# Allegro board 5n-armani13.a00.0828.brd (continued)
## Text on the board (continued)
VCC: list("[Spacing] VCC" "47.Shape to Route Keepin" "0 MIL [DEFAULT]" "0 MIL" "0.00 MIL" "DRC ERROR CLASS/VCC" "[Shape] Route Keepin/All ((-191.01 273.9) (8699.38 4792.96))" "[Vcc Shape] GND ((-191.01 273.9) (8699.38 4792.96))" list(-172.450000 3468.870000) nil)@@@list("iris_chen" "2017/08/23 17:49:25" nil "P16C000357-PC" "5n-armani13.a00")@@@list("anson_lee" "2017/08/24 14:21:24" nil "P172000029-PC" "5n-armani13.a00.0824") | list("[Spacing] VCC" "54.Shape to Route Keepin" "0 MIL [DEFAULT]" "0 MIL" "0.00 MIL" "DRC ERROR CLASS/VCC" "[Shape] Route Keepin/All ((-191.01 273.9) (8699.38 4792.96))" "[Vcc Shape] AGND ((-137.46 1141.0) (434.0 2428.0))" list(-129.620000 2286.830000) nil)@@@list("iris_chen" "2017/08/22 17:13:19" nil "P16C000357-PC" "5n-armani13.a00")@@@list("anson_lee" "2017/08/24 14:21:29" nil "P172000029-PC" "5n-armani13.a00.0824") | list("[Spacing] VCC" "143.Thru Pin to Shape" "5 MIL [DEFAULT]" "0 MIL" "5.00 MIL" "DRC ERROR CLASS/VCC" "[ThruPin] GND (<uTiL>cId30<uTiL>.51) (380.5 1405.0)" "[Vcc Shape] +5VSB ((381.0 745.0) (7865.0 3971.0))" list(381.000000 1416.990000) nil)@@@list("iris_chen" "2017/08/22 17:17:54" nil "P16C000357-PC" "5n-armani13.a00")@@@list("anson_lee" "2017/08/24 14:22:26" nil "P172000029-PC" "5n-armani13.a00.0824") | list("[Spacing] VCC" "142.Thru Pin to Shape" "5 MIL [DEFAULT]" "0 MIL" "5.00 MIL" "DRC ERROR CLASS/VCC" "[ThruPin] GND (<uTiL>cId30<uTiL>.52) (380.5 1325.5)" "[Vcc Shape] +5VSB ((381.0 745.0) (7865.0 3971.0))" list(381.000000 1337.490000) nil)@@@list("iris_chen" "2017/08/22 17:17:54" nil "P16C000357-PC" "5n-armani13.a00")@@@list("anson_lee" "2017/08/24 14:22:25" nil "P172000029-PC" "5n-armani13.a00.0824") | list("[Spacing] VCC" "145.Thru Pin to Shape" "5 MIL [DEFAULT]" "0 MIL" "5.00 MIL" "DRC ERROR CLASS/VCC" "[ThruPin] GND (<uTiL>cId30<uTiL>.50) (380.5 1484.5)" "[Vcc Shape] +5VSB ((381.0 745.0) (7865.0 3971.0))" list(392.490000 1484.000000) nil)@@@list("iris_chen" "2017/08/22 17:17:55" nil "P16C000357-PC" "5n-armani13.a00")@@@list("anson_lee" "2017/08/24 14:22:36" nil "P172000029-PC" "5n-armani13.a00.0824") | list("[Spacing] VCC" "96.Shape to Thru Via" "5 MIL [DEFAULT]" "0 MIL" "5.00 MIL" "DRC ERROR CLASS/VCC" "[ThruVia] DP2_MUX (VIA20D10A30) (401.0 3686.0)" "[Vcc Shape] +USB_TYPEC ((30.0 3558.96) (393.07 3902.29))" list(393.070000 3692.090000) nil)@@@list("iris_chen" "2017/08/22 17:13:04" nil "P16C000357-PC" "5n-armani13.a00")@@@list("anson_lee" "2017/08/24 14:21:54" nil "P172000029-PC" "5n-armani13.a00.0824") | list("[Spacing] VCC" "44.Shape to Thru Via" "5 MIL [DEFAULT]" "0 MIL" "5.00 MIL" "DRC ERROR CLASS/VCC" "[ThruVia] DP2_MUX (VIA20D10A30) (401.0 3686.0)" "[Vcc Shape] GND ((-191.01 273.9) (8699.38 4792.96))" list(403.070000 3695.780000) nil)@@@list("iris_chen" "2017/08/22 17:13:25" nil "P16C000357-PC" "5n-armani13.a00")@@@list("anson_lee" "2017/08/24 14:21:22" nil "P172000029-PC" "5n-armani13.a00.0824") | list("[Spacing-SameNet] VCC" "189.Shape to Thru Via Same Net" "5 MIL [DEFAULT]" "0 MIL" "5.00 MIL" "DRC ERROR CLASS/VCC" "[ThruVia] GND (VIA20D10A30) (455.0 3250.0)" "[Vcc Shape] GND ((-191.01 273.9) (8699.38 4792.96))" list(451.000000 3259.170000) nil)@@@list("iris_chen" "2017/08/22 17:18:45" nil "P16C000357-PC" "5n-armani13.a00")@@@list("anson_lee" "2017/08/24 14:23:58" nil "P172000029-PC" "5n-armani13.a00.0824") | list("[Spacing-SameNet] VCC" "190.Shape to Thru Via Same Net" "5 MIL [DEFAULT]" "0 MIL" "5.00 MIL" "DRC ERROR CLASS/VCC" "[ThruVia] GND (VIA20D10A30) (456.54 3173.14)" "[Vcc Shape] GND ((-191.01 273.9) (8699.38 4792.96))" list(451.000000 3181.470000) nil)@@@list("iris_chen" "2017/08/22 17:18:45" nil "P16C000357-PC" "5n-armani13.a00")@@@list("anson_lee" "2017/08/24 14:23:59" nil "P172000029-PC" "5n-armani13.a00.0824") | list("[Spacing] VCC" "147.Shape to Thru Via" "5 MIL [DEFAULT]" "0 MIL" "5.00 MIL" "DRC ERROR CLASS/VCC" "[ThruVia] GND (VIA20D10A30) (455.0 3250.0)" "[Vcc Shape] +5VSB ((381.0 745.0) (7865.0 3971.0))" list(461.000000 3258.000000) nil)@@@list("iris_chen" "2017/08/22 17:17:56" nil "P16C000357-PC" "5n-armani13.a00")@@@list("anson_lee" "2017/08/24 14:22:38" nil "P172000029-PC" "5n-armani13.a00.0824") | list("[Spacing] VCC" "148.Shape to Thru Via" "5 MIL [DEFAULT]" "0 MIL" "5.00 MIL" "DRC ERROR CLASS/VCC" "[ThruVia] GND (VIA20D10A30) (456.54 3173.14)" "[Vcc Shape] +5VSB ((381.0 745.0) (7865.0 3971.0))" list(461.000000 3182.090000) nil)@@@list("iris_chen" "2017/08/22 17:17:57" nil "P16C000357-PC" "5n-armani13.a00")@@@list("anson_lee" "2017/08/24 14:22:38" nil "P172000029-PC" "5n-armani13.a00.0824") | list("[Spacing-SameNet] VCC" "192.Thru Pin to Shape Same Net" "5 MIL [DEFAULT]" "0 MIL" "5.00 MIL" "DRC ERROR CLASS/VCC" "[ThruPin] GND (<uTiL>cId2509<uTiL>.23) (504.69 3399.31)" "[Vcc Shape] GND ((-191.01 273.9) (8699.38 4792.96))" list(492.750000 3400.470000) nil)@@@list("iris_chen" "2017/08/22 17:18:46" nil "P16C000357-PC" "5n-armani13.a00")@@@list("anson_lee" "2017/08/24 14:24:00" nil "P172000029-PC" "5n-armani13.a00.0824") | list("[Spacing-SameNet] VCC" "191.Thru Pin to Shape Same Net" "5 MIL [DEFAULT]" "0 MIL" "5.00 MIL" "DRC ERROR CLASS/VCC" "[ThruPin] GND (<uTiL>cId2509<uTiL>.26) (504.69 3438.69)" "[Vcc Shape] GND ((-191.01 273.9) (8699.38 4792.96))" list(496.000000 3446.970000) nil)@@@list("iris_chen" "2017/08/22 17:18:45" nil "P16C000357-PC" "5n-armani13.a00")@@@list("anson_lee" "2017/08/24 14:23:59" nil "P172000029-PC" "5n-armani13.a00.0824") | list("[Spacing] VCC" "149.Thru Pin to Shape" "5 MIL [DEFAULT]" "0 MIL" "5.00 MIL" "DRC ERROR CLASS/VCC" "[ThruPin] GND (<uTiL>cId2509<uTiL>.26) (504.69 3438.69)" "[Vcc Shape] +5VSB ((381.0 745.0) (7865.0 3971.0))" list(506.000000 3450.620000) nil)@@@list("iris_chen" "2017/08/22 17:17:57" nil "P16C000357-PC" "5n-armani13.a00")@@@list("anson_lee" "2017/08/24 14:22:39" nil "P172000029-PC" "5n-armani13.a00.0824") | list("[Spacing] VCC" "150.Thru Pin to Shape" "5 MIL [DEFAULT]" "0 MIL" "5.00 MIL" "DRC ERROR CLASS/VCC" "[ThruPin] GND (<uTiL>cId2509<uTiL>.23) (504.69 3399.31)" "[Vcc Shape] +5VSB ((381.0 745.0) (7865.0 3971.0))" list(506.000000 3411.240000) nil)@@@list("iris_chen" "2017/08/22 17:17:58" nil "P16C000357-PC" "5n-armani13.a00")@@@list("anson_lee" "2017/08/24 14:22:40" nil "P172000029-PC" "5n-armani13.a00.0824") | list("[Spacing] VCC" "134.Shape to Thru Via" "5 MIL [DEFAULT]" "0 MIL" "5.00 MIL" "DRC ERROR CLASS/VCC" "[ThruVia] CHG_ACIN (VIA20D10A30) (847.0 1064.0)" "[Vcc Shape] +5VSB ((381.0 745.0) (7865.0 3971.0))" list(855.000000 1070.000000) nil)@@@list("iris_chen" "2017/08/22 17:17:50" nil "P16C000357-PC" "5n-armani13.a00")@@@list("anson_lee" "2017/08/24 14:22:21" nil "P172000029-PC" "5n-armani13.a00.0824") | list("[Spacing] VCC" "43.Shape to Thru Via" "5 MIL [DEFAULT]" "0 MIL" "5.00 MIL" "DRC ERROR CLASS/VCC" "[ThruVia] CHG_ACIN (VIA20D10A30) (847.0 1064.0)" "[Vcc Shape] GND ((-191.01 273.9) (8699.38 4792.96))" list(856.170000 1060.000000) nil)@@@list("iris_chen" "2017/08/22 17:13:24" nil "P16C000357-PC" "5n-armani13.a00")@@@list("anson_lee" "2017/08/24 14:21:22" nil "P172000029-PC" "5n-armani13.a00.0824") | list("[Spacing] VCC" "48.Shape to Thru Via" "5 MIL [DEFAULT]" "0 MIL" "5.00 MIL" "DRC ERROR CLASS/VCC" "[ThruVia] HDMI_HPD_SNK (VIA20D10A30) (954.0 2921.0)" "[Vcc Shape] +1P8VSB ((880.0 2930.0) (3605.0 4684.0))" list(958.360000 2930.000000) nil)@@@list("iris_chen" "2017/08/22 17:13:27" nil "P16C000357-PC" "5n-armani13.a00")@@@list("anson_lee" "2017/08/24 14:21:25" nil "P172000029-PC" "5n-armani13.a00.0824") | list("[Spacing] VCC" "124.Shape to Thru Via" "5 MIL [DEFAULT]" "0 MIL" "5.00 MIL" "DRC ERROR CLASS/VCC" "[ThruVia] HDMI_HPD_SNK (VIA20D10A30) (954.0 2921.0)" "[Vcc Shape] +3P3VSB ((926.0 394.17) (8430.0 4743.0))" list(963.950000 2920.000000) nil)@@@list("iris_chen" "2017/08/22 17:18:16" nil "P16C000357-PC" "5n-armani13.a00")@@@list("anson_lee" "2017/08/24 14:22:16" nil "P172000029-PC" "5n-armani13.a00.0824") | list("[Spacing] VCC" "77.Shape to Thru Via" "5 MIL [DEFAULT]" "0 MIL" "5.00 MIL" "DRC ERROR CLASS/VCC" "[ThruVia] +VCCPLL_OC (VIA20D10A30) (1048.0 2923.0)" "[Vcc Shape] +1P8VSB ((880.0 2930.0) (3605.0 4684.0))" list(1055.140000 2930.000000) nil)@@@list("iris_chen" "2017/08/22 17:13:28" nil "P16C000357-PC" "5n-armani13.a00")@@@nil | list("[Spacing] VCC" "141.Shape to Thru Via" "5 MIL [DEFAULT]" "0 MIL" "5.00 MIL" "DRC ERROR CLASS/VCC" "[ThruVia] +VCCPLL_OC (VIA20D10A30) (1048.0 2923.0)" "[Vcc Shape] +3P3VSB ((926.0 394.17) (8430.0 4743.0))" list(1057.540000 2920.000000) nil)@@@list("iris_chen" "2017/08/22 17:18:16" nil "P16C000357-PC" "5n-armani13.a00")@@@nil | list("[Spacing] VCC" "50.Shape to Thru Via" "5 MIL [DEFAULT]" "0 MIL" "5.00 MIL" "DRC ERROR CLASS/VCC" "[ThruVia] +VDC_IN (VIA20D10A30) (1266.0 3886.0)" "[Vcc Shape] +1P8VSB ((880.0 2930.0) (3605.0 4684.0))" list(1265.000000 3895.950000) nil)@@@list("iris_chen" "2017/08/22 17:17:46" nil "P16C000357-PC" "5n-armani13.a00")@@@list("anson_lee" "2017/08/24 14:21:26" nil "P172000029-PC" "5n-armani13.a00.0824") | list("[Spacing] VCC" "49.Shape to Thru Via" "5 MIL [DEFAULT]" "0 MIL" "5.00 MIL" "DRC ERROR CLASS/VCC" "[ThruVia] GND (VIA20D10A30) (1269.0 3139.0)" "[Vcc Shape] +1P8VSB ((880.0 2930.0) (3605.0 4684.0))" list(1265.000000 3148.170000) nil)@@@list("iris_chen" "2017/08/22 17:17:45" nil "P16C000357-PC" "5n-armani13.a00")@@@list("anson_lee" "2017/08/24 14:21:26" nil "P172000029-PC" "5n-armani13.a00.0824") | list("[Spacing] VCC" "128.Shape to Thru Via" "5 MIL [DEFAULT]" "0 MIL" "5.00 MIL" "DRC ERROR CLASS/VCC" "[ThruVia] +VDC_IN (VIA20D10A30) (1266.0 3886.0)" "[Vcc Shape] +3P3VSB ((926.0 394.17) (8430.0 4743.0))" list(1275.000000 3890.360000) nil)@@@list("iris_chen" "2017/08/22 17:18:18" nil "P16C000357-PC" "5n-armani13.a00")@@@list("anson_lee" "2017/08/24 14:22:18" nil "P172000029-PC" "5n-armani13.a00.0824") | list("[Spacing] VCC" "125.Shape to Thru Via" "5 MIL [DEFAULT]" "0 MIL" "5.00 MIL" "DRC ERROR CLASS/VCC" "[ThruVia] GND (VIA20D10A30) (1269.0 3139.0)" "[Vcc Shape] +3P3VSB ((926.0 394.17) (8430.0 4743.0))" list(1275.000000 3147.000000) nil)@@@list("iris_chen" "2017/08/22 17:18:17" nil "P16C000357-PC" "5n-armani13.a00")@@@list("anson_lee" "2017/08/24 14:22:16" nil "P172000029-PC" "5n-armani13.a00.0824") | list("[Spacing] VCC" "51.Shape to Thru Via" "5 MIL [DEFAULT]" "0 MIL" "5.00 MIL" "DRC ERROR CLASS/VCC" "[ThruVia] USB_ADT (VIA20D10A30) (1335.0 4439.0)" "[Vcc Shape] +1P8VSB ((880.0 2930.0) (3605.0 4684.0))" list(1343.000000 4445.000000) nil)@@@list("iris_chen" "2017/08/22 17:17:47" nil "P16C000357-PC" "5n-armani13.a00")@@@list("anson_lee" "2017/08/24 14:21:27" nil "P172000029-PC" "5n-armani13.a00.0824") | list("[Spacing] VCC" "129.Shape to Thru Via" "5 MIL [DEFAULT]" "0 MIL" "5.00 MIL" "DRC ERROR CLASS/VCC" "[ThruVia] USB_ADT (VIA20D10A30) (1335.0 4439.0)" "[Vcc Shape] +3P3VSB ((926.0 394.17) (8430.0 4743.0))" list(1344.170000 4435.000000) nil)@@@list("iris_chen" "2017/08/22 17:18:19" nil "P16C000357-PC" "5n-armani13.a00")@@@list("anson_lee" "2017/08/24 14:22:18" nil "P172000029-PC" "5n-armani13.a00.0824") | list("[Spacing] VCC" "144.Shape to Thru Via" "5 MIL [DEFAULT]" "0 MIL" "5.00 MIL" "DRC ERROR CLASS/VCC" "[ThruVia] +3VALW_EC (VIA20D10A30) (1565.0 1414.0)" "[Vcc Shape] +5VSB ((381.0 745.0) (7865.0 3971.0))" list(1568.350000 1404.580000) nil)@@@list("iris_chen" "2017/08/22 17:17:55" nil "P16C000357-PC" "5n-armani13.a00")@@@list("anson_lee" "2017/08/24 14:22:26" nil "P172000029-PC" "5n-armani13.a00.0824") | list("[Spacing] VCC" "121.Shape to Thru Via" "5 MIL [DEFAULT]" "0 MIL" "5.00 MIL" "DRC ERROR CLASS/VCC" "[ThruVia] +3VALW_EC (VIA20D10A30) (1565.0 1414.0)" "[Vcc Shape] +3P3VSB ((926.0 394.17) (8430.0 4743.0))" list(1574.840000 1412.240000) nil)@@@list("iris_chen" "2017/08/22 17:18:13" nil "P16C000357-PC" "5n-armani13.a00")@@@list("anson_lee" "2017/08/24 14:22:14" nil "P172000029-PC" "5n-armani13.a00.0824") | list("[Spacing] VCC" "109.Shape to Thru Via" "5 MIL [DEFAULT]" "0 MIL" "5.00 MIL" "DRC ERROR CLASS/VCC" "[ThruVia] GND (VIA20D10A30) (1789.09 521.9)" "[Vcc Shape] +3P3VSB ((926.0 394.17) (8430.0 4743.0))" list(1796.330000 515.000000) nil)@@@list("iris_chen" "2017/08/22 17:18:08" nil "P16C000357-PC" "5n-armani13.a00")@@@list("anson_lee" "2017/08/24 14:22:03" nil "P172000029-PC" "5n-armani13.a00.0824") | list("[Spacing] VCC" "61.Shape to Thru Via" "5 MIL [DEFAULT]" "0 MIL" "5.00 MIL" "DRC ERROR CLASS/VCC" "[ThruVia] GND (VIA20D10A30) (1789.09 521.9)" "[Vcc Shape] +5V ((625.0 525.0) (8000.0 2265.0))" list(1798.600000 525.000000) nil)@@@list("iris_chen" "2017/08/22 17:13:05" nil "P16C000357-PC" "5n-armani13.a00")@@@list("anson_lee" "2017/08/24 14:21:33" nil "P172000029-PC" "5n-armani13.a00.0824") | list("[Spacing] VCC" "108.Shape to Thru Via" "5 MIL [DEFAULT]" "0 MIL" "5.00 MIL" "DRC ERROR CLASS/VCC" "[ThruVia] +3P3V_PAD (VIA20D10A30) (1814.0 524.76)" "[Vcc Shape] +3P3VSB ((926.0 394.17) (8430.0 4743.0))" list(1816.180000 515.000000) nil)@@@list("iris_chen" "2017/08/22 17:18:07" nil "P16C000357-PC" "5n-armani13.a00")@@@list("anson_lee" "2017/08/24 14:22:02" nil "P172000029-PC" "5n-armani13.a00.0824") | list("[Spacing] VCC" "60.Shape to Thru Via" "5 MIL [DEFAULT]" "0 MIL" "5.00 MIL" "DRC ERROR CLASS/VCC" "[ThruVia] +3P3V_PAD (VIA20D10A30) (1814.0 524.76)" "[Vcc Shape] +5V ((625.0 525.0) (8000.0 2265.0))" list(1824.000000 525.000000) nil)@@@list("iris_chen" "2017/08/22 17:13:04" nil "P16C000357-PC" "5n-armani13.a00")@@@list("anson_lee" "2017/08/24 14:21:33" nil "P172000029-PC" "5n-armani13.a00.0824") | list("[Spacing] VCC" "110.Shape to Thru Via" "5 MIL [DEFAULT]" "0 MIL" "5.00 MIL" "DRC ERROR CLASS/VCC" "[ThruVia] +3P3V_PAD (VIA20D10A30) (1860.0 524.0)" "[Vcc Shape] +3P3VSB ((926.0 394.17) (8430.0 4743.0))" list(1864.360000 515.000000) nil)@@@list("iris_chen" "2017/08/22 17:18:08" nil "P16C000357-PC" "5n-armani13.a00")@@@list("anson_lee" "2017/08/24 14:22:04" nil "P172000029-PC" "5n-armani13.a00.0824") | list("[Spacing] VCC" "62.Shape to Thru Via" "5 MIL [DEFAULT]" "0 MIL" "5.00 MIL" "DRC ERROR CLASS/VCC" "[ThruVia] +3P3V_PAD (VIA20D10A30) (1860.0 524.0)" "[Vcc Shape] +5V ((625.0 525.0) (8000.0 2265.0))" list(1869.950000 525.000000) nil)@@@list("iris_chen" "2017/08/22 17:13:06" nil "P16C000357-PC" "5n-armani13.a00")@@@list("anson_lee" "2017/08/24 14:21:34" nil "P172000029-PC" "5n-armani13.a00.0824") | list("[Spacing] VCC" "111.Shape to Thru Via" "5 MIL [DEFAULT]" "0 MIL" "5.00 MIL" "DRC ERROR CLASS/VCC" "[ThruVia] GND (VIA20D10A30) (1895.0 522.0)" "[Vcc Shape] +3P3VSB ((926.0 394.17) (8430.0 4743.0))" list(1902.140000 515.000000) nil)@@@list("iris_chen" "2017/08/22 17:18:08" nil "P16C000357-PC" "5n-armani13.a00")@@@list("anson_lee" "2017/08/24 14:22:04" nil "P172000029-PC" "5n-armani13.a00.0824") | list("[Spacing] VCC" "63.Shape to Thru Via" "5 MIL [DEFAULT]" "0 MIL" "5.00 MIL" "DRC ERROR CLASS/VCC" "[ThruVia] GND (VIA20D10A30) (1895.0 522.0)" "[Vcc Shape] +5V ((625.0 525.0) (8000.0 2265.0))" list(1904.540000 525.000000) nil)@@@list("iris_chen" "2017/08/22 17:13:06" nil "P16C000357-PC" "5n-armani13.a00")@@@list("anson_lee" "2017/08/24 14:21:34" nil "P172000029-PC" "5n-armani13.a00.0824") | list("[Spacing] VCC" "112.Shape to Thru Via" "5 MIL [DEFAULT]" "0 MIL" "5.00 MIL" "DRC ERROR CLASS/VCC" "[ThruVia] GND (VIA20D10A30) (2015.0 524.0)" "[Vcc Shape] +3P3VSB ((926.0 394.17) (8430.0 4743.0))" list(2019.360000 515.000000) nil)@@@list("iris_chen" "2017/08/22 17:18:09" nil "P16C000357-PC" "5n-armani13.a00")@@@list("anson_lee" "2017/08/24 14:22:06" nil "P172000029-PC" "5n-armani13.a00.0824") | list("[Spacing] VCC" "64.Shape to Thru Via" "5 MIL [DEFAULT]" "0 MIL" "5.00 MIL" "DRC ERROR CLASS/VCC" "[ThruVia] GND (VIA20D10A30) (2015.0 524.0)" "[Vcc Shape] +5V ((625.0 525.0) (8000.0 2265.0))" list(2024.950000 525.000000) nil)@@@list("iris_chen" "2017/08/22 17:13:07" nil "P16C000357-PC" "5n-armani13.a00")@@@list("anson_lee" "2017/08/24 14:21:35" nil "P172000029-PC" "5n-armani13.a00.0824") | list("[Spacing] VCC" "45.Shape to Thru Via" "5 MIL [DEFAULT]" "0 MIL" "5.00 MIL" "DRC ERROR CLASS/VCC" "[ThruVia] AD_OFF_R (VIA20D10A30) (2034.0 4606.0)" "[Vcc Shape] GND ((-191.01 273.9) (8699.38 4792.96))" list(2042.000000 4612.000000) nil)@@@list("iris_chen" "2017/08/22 17:13:25" nil "P16C000357-PC" "5n-armani13.a00")@@@list("anson_lee" "2017/08/24 14:21:23" nil "P172000029-PC" "5n-armani13.a00.0824") | list("[Spacing] VCC" "52.Shape to Thru Via" "5 MIL [DEFAULT]" "0 MIL" "5.00 MIL" "DRC ERROR CLASS/VCC" "[ThruVia] AD_OFF_R (VIA20D10A30) (2034.0 4606.0)" "[Vcc Shape] +1P8VSB ((880.0 2930.0) (3605.0 4684.0))" list(2043.170000 4602.000000) nil)@@@list("iris_chen" "2017/08/22 17:17:48" nil "P16C000357-PC" "5n-armani13.a00")@@@list("anson_lee" "2017/08/24 14:21:27" nil "P172000029-PC" "5n-armani13.a00.0824") | list("[Spacing] VCC" "114.Shape to Thru Via" "5 MIL [DEFAULT]" "0 MIL" "5.00 MIL" "DRC ERROR CLASS/VCC" "[ThruVia] RESET_OUT# (VIA20D10A30) (2069.0 1059.3)" "[Vcc Shape] +3P3VSB ((926.0 394.17) (8430.0 4743.0))" list(2077.220000 1065.000000) nil)@@@list("iris_chen" "2017/08/22 17:18:10" nil "P16C000357-PC" "5n-armani13.a00")@@@list("anson_lee" "2017/08/24 14:22:10" nil "P172000029-PC" "5n-armani13.a00.0824") | list("[Spacing] VCC" "135.Shape to Thru Via" "5 MIL [DEFAULT]" "0 MIL" "5.00 MIL" "DRC ERROR CLASS/VCC" "[ThruVia] RESET_OUT# (VIA20D10A30) (2069.0 1059.3)" "[Vcc Shape] +5VSB ((381.0 745.0) (7865.0 3971.0))" list(2078.030000 1055.000000) nil)@@@list("iris_chen" "2017/08/22 17:17:50" nil "P16C000357-PC" "5n-armani13.a00")@@@list("anson_lee" "2017/08/24 14:22:21" nil "P172000029-PC" "5n-armani13.a00.0824") | list("[Spacing] VCC" "46.Shape to Thru Via" "5 MIL [DEFAULT]" "0 MIL" "5.00 MIL" "DRC ERROR CLASS/VCC" "[ThruVia] N146992205 (VIA20D10A30) (2568.0 4606.0)" "[Vcc Shape] GND ((-191.01 273.9) (8699.38 4792.96))" list(2576.000000 4612.000000) nil)@@@list("iris_chen" "2017/08/22 17:13:26" nil "P16C000357-PC" "5n-armani13.a00")@@@list("anson_lee" "2017/08/24 14:21:24" nil "P172000029-PC" "5n-armani13.a00.0824") | list("[Spacing] VCC" "53.Shape to Thru Via" "5 MIL [DEFAULT]" "0 MIL" "5.00 MIL" "DRC ERROR CLASS/VCC" "[ThruVia] N146992205 (VIA20D10A30) (2568.0 4606.0)" "[Vcc Shape] +1P8VSB ((880.0 2930.0) (3605.0 4684.0))" list(2577.170000 4602.000000) nil)@@@list("iris_chen" "2017/08/22 17:17:48" nil "P16C000357-PC" "5n-armani13.a00")@@@list("anson_lee" "2017/08/24 14:21:28" nil "P172000029-PC" "5n-armani13.a00.0824") | list("[Spacing] VCC" "115.Shape to Thru Via" "5 MIL [DEFAULT]" "0 MIL" "5.00 MIL" "DRC ERROR CLASS/VCC" "[ThruVia] +1P8V (VIA30D18A40) (3275.0 1142.0)" "[Vcc Shape] +3P3VSB ((926.0 394.17) (8430.0 4743.0))" list(3288.270000 1149.000000) nil)@@@list("iris_chen" "2017/08/22 17:18:10" nil "P16C000357-PC" "5n-armani13.a00")@@@list("anson_lee" "2017/08/24 14:22:11" nil "P172000029-PC" "5n-armani13.a00.0824") | list("[Spacing] VCC" "136.Shape to Thru Via" "5 MIL [DEFAULT]" "0 MIL" "5.00 MIL" "DRC ERROR CLASS/VCC" "[ThruVia] +1P8V (VIA30D18A40) (3275.0 1142.0)" "[Vcc Shape] +5VSB ((381.0 745.0) (7865.0 3971.0))" list(3289.700000 1139.000000) nil)@@@list("iris_chen" "2017/08/22 17:17:51" nil "P16C000357-PC" "5n-armani13.a00")@@@list("anson_lee" "2017/08/24 14:22:22" nil "P172000029-PC" "5n-armani13.a00.0824") | list("[Spacing] VCC" "75.Shape to Route Keepin" "0 MIL [DEFAULT]" "0 MIL" "0.00 MIL" "DRC ERROR CLASS/VCC" "[Shape] Route Keepin/All ((-191.01 273.9) (8699.38 4792.96))" "[Vcc Shape] GND ((-191.01 273.9) (8699.38 4792.96))" list(3404.430000 4702.410000) nil)@@@list("iris_chen" "2017/08/22 17:13:26" nil "P16C000357-PC" "5n-armani13.a00")@@@nil | list("[Spacing-SameNet] VCC" "194.Shape to Thru Via Same Net" "5 MIL [DEFAULT]" "0 MIL" "5.00 MIL" "DRC ERROR CLASS/VCC" "[ThruVia] GND (VIA18D10A28) (3880.45 2091.55)" "[Vcc Shape] GND ((2160.0 1185.0) (4422.0 3926.0))" list(3872.390000 2095.540000) nil)@@@list("iris_chen" "2017/08/22 17:18:44" nil "P16C000357-PC" "5n-armani13.a00")@@@list("anson_lee" "2017/08/24 14:24:01" nil "P172000029-PC" "5n-armani13.a00.0824") | list("[Spacing] VCC" "57.Shape to Thru Via" "5 MIL [DEFAULT]" "0 MIL" "5.00 MIL" "DRC ERROR CLASS/VCC" "[ThruVia] +1P2V_DUAL (VIA18D10A28) (3883.0 2036.0)" "[Vcc Shape] GND ((2160.0 1185.0) (4422.0 3926.0))" list(3875.000000 2040.120000) nil)@@@list("iris_chen" "2017/08/22 17:13:21" nil "P16C000357-PC" "5n-armani13.a00")@@@list("anson_lee" "2017/08/24 14:21:31" nil "P172000029-PC" "5n-armani13.a00.0824") | list("[Spacing] VCC" "88.Shape to Thru Via" "5 MIL [DEFAULT]" "0 MIL" "5.00 MIL" "DRC ERROR CLASS/VCC" "[ThruVia] GND (VIA18D10A28) (3880.45 2091.55)" "[Vcc Shape] +VCCIO ((3836.0 1141.93) (5170.0 2510.0))" list(3881.600000 2100.480000) nil)@@@list("iris_chen" "2017/08/22 17:18:04" nil "P16C000357-PC" "5n-armani13.a00")@@@list("anson_lee" "2017/08/24 14:21:48" nil "P172000029-PC" "5n-armani13.a00.0824") | list("[Spacing] VCC" "87.Shape to Thru Via" "5 MIL [DEFAULT]" "0 MIL" "5.00 MIL" "DRC ERROR CLASS/VCC" "[ThruVia] +1P2V_DUAL (VIA18D10A28) (3883.0 2036.0)" "[Vcc Shape] +VCCIO ((3836.0 1141.93) (5170.0 2510.0))" list(3885.000000 2044.770000) nil)@@@list("iris_chen" "2017/08/22 17:18:03" nil "P16C000357-PC" "5n-armani13.a00")@@@list("anson_lee" "2017/08/24 14:21:47" nil "P172000029-PC" "5n-armani13.a00.0824") | list("[Spacing] VCC" "59.Shape to Thru Via" "5 MIL [DEFAULT]" "0 MIL" "5.00 MIL" "DRC ERROR CLASS/VCC" "[ThruVia] SIO_SLP_S4# (VIA20D10A30) (3897.46 3779.46)" "[Vcc Shape] GND ((2160.0 1185.0) (4422.0 3926.0))" list(3900.110000 3769.820000) nil)@@@list("iris_chen" "2017/08/22 17:13:23" nil "P16C000357-PC" "5n-armani13.a00")@@@list("anson_lee" "2017/08/24 14:21:32" nil "P172000029-PC" "5n-armani13.a00.0824") | list("[Spacing] VCC" "127.Shape to Thru Via" "5 MIL [DEFAULT]" "0 MIL" "5.00 MIL" "DRC ERROR CLASS/VCC" "[ThruVia] SIO_SLP_S4# (VIA20D10A30) (3897.46 3779.46)" "[Vcc Shape] +3P3VSB ((926.0 394.17) (8430.0 4743.0))" list(3907.140000 3776.940000) nil)@@@list("iris_chen" "2017/08/22 17:18:18" nil "P16C000357-PC" "5n-armani13.a00")@@@list("anson_lee" "2017/08/24 14:22:17" nil "P172000029-PC" "5n-armani13.a00.0824") | list("[Spacing-SameNet] VCC" "195.Shape to Thru Via Same Net" "5 MIL [DEFAULT]" "0.88 MIL" "4.12 MIL" "DRC ERROR CLASS/VCC" "[ThruVia] GND (VIA18D10A28) (4019.88 2419.5)" "[Vcc Shape] GND ((2160.0 1185.0) (4422.0 3926.0))" list(4010.880000 2419.500000) nil)@@@list("iris_chen" "2017/08/22 17:18:44" nil "P16C000357-PC" "5n-armani13.a00")@@@list("anson_lee" "2017/08/24 14:24:02" nil "P172000029-PC" "5n-armani13.a00.0824") | list("[Spacing] VCC" "58.Shape to Thru Via" "5 MIL [DEFAULT]" "0 MIL" "5.00 MIL" "DRC ERROR CLASS/VCC" "[ThruVia] +1P2V_DUAL (VIA18D10A28) (4019.88 2456.0)" "[Vcc Shape] GND ((2160.0 1185.0) (4422.0 3926.0))" list(4011.150000 2458.200000) nil)@@@list("iris_chen" "2017/08/22 17:13:22" nil "P16C000357-PC" "5n-armani13.a00")@@@list("anson_lee" "2017/08/24 14:21:31" nil "P172000029-PC" "5n-armani13.a00.0824") | list("[Spacing] VCC" "89.Shape to Thru Via" "5 MIL [DEFAULT]" "0 MIL" "5.00 MIL" "DRC ERROR CLASS/VCC" "[ThruVia] +1P2V_DUAL (VIA18D10A28) (4019.88 2456.0)" "[Vcc Shape] +VCCIO ((3836.0 1141.93) (5170.0 2510.0))" list(4020.000000 2447.000000) nil)@@@list("iris_chen" "2017/08/22 17:18:04" nil "P16C000357-PC" "5n-armani13.a00")@@@list("anson_lee" "2017/08/24 14:21:49" nil "P172000029-PC" "5n-armani13.a00.0824") | list("[Spacing] VCC" "90.Shape to Thru Via" "5 MIL [DEFAULT]" "0 MIL" "5.00 MIL" "DRC ERROR CLASS/VCC" "[ThruVia] GND (VIA18D10A28) (4019.88 2419.5)" "[Vcc Shape] +VCCIO ((3836.0 1141.93) (5170.0 2510.0))" list(4020.000000 2428.500000) nil)@@@list("iris_chen" "2017/08/22 17:18:05" nil "P16C000357-PC" "5n-armani13.a00")@@@list("anson_lee" "2017/08/24 14:21:50" nil "P172000029-PC" "5n-armani13.a00.0824") | list("[Spacing] VCC" "120.Shape to Thru Via" "5 MIL [DEFAULT]" "0 MIL" "5.00 MIL" "DRC ERROR CLASS/VCC" "[ThruVia] +VCC_RTC_PCH (VIA20D10A30) (4067.0 1209.61)" "[Vcc Shape] +3P3VSB ((926.0 394.17) (8430.0 4743.0))" list(4069.770000 1200.000000) nil)@@@list("iris_chen" "2017/08/22 17:18:13" nil "P16C000357-PC" "5n-armani13.a00")@@@list("anson_lee" "2017/08/24 14:22:14" nil "P172000029-PC" "5n-armani13.a00.0824") | list("[Spacing] VCC" "84.Shape to Thru Via" "5 MIL [DEFAULT]" "0 MIL" "5.00 MIL" "DRC ERROR CLASS/VCC" "[ThruVia] +VCC_RTC_PCH (VIA20D10A30) (4067.0 1209.61)" "[Vcc Shape] +VCCIO ((3836.0 1141.93) (5170.0 2510.0))" list(4076.990000 1210.000000) nil)@@@list("iris_chen" "2017/08/22 17:18:02" nil "P16C000357-PC" "5n-armani13.a00")@@@list("anson_lee" "2017/08/24 14:21:46" nil "P172000029-PC" "5n-armani13.a00.0824") | list("[Spacing] VCC" "137.Shape to Thru Via" "5 MIL [DEFAULT]" "0 MIL" "5.00 MIL" "DRC ERROR CLASS/VCC" "[ThruVia] +1P8VSB (VIA20D10A30) (4175.0 1088.0)" "[Vcc Shape] +5VSB ((381.0 745.0) (7865.0 3971.0))" list(4181.000000 1080.000000) nil)@@@list("iris_chen" "2017/08/22 17:17:51" nil "P16C000357-PC" "5n-armani13.a00")@@@list("anson_lee" "2017/08/24 14:22:22" nil "P172000029-PC" "5n-armani13.a00.0824") | list("[Spacing] VCC" "116.Shape to Thru Via" "5 MIL [DEFAULT]" "0 MIL" "5.00 MIL" "DRC ERROR CLASS/VCC" "[ThruVia] +1P8VSB (VIA20D10A30) (4175.0 1088.0)" "[Vcc Shape] +3P3VSB ((926.0 394.17) (8430.0 4743.0))" list(4184.800000 1090.000000) nil)@@@list("iris_chen" "2017/08/22 17:18:11" nil "P16C000357-PC" "5n-armani13.a00")@@@list("anson_lee" "2017/08/24 14:22:11" nil "P172000029-PC" "5n-armani13.a00.0824") | list("[Spacing] VCC" "65.Shape to Thru Via" "5 MIL [DEFAULT]" "0 MIL" "5.00 MIL" "DRC ERROR CLASS/VCC" "[ThruVia] GND (VIA20D10A30) (4188.35 899.5)" "[Vcc Shape] +5V ((625.0 525.0) (8000.0 2265.0))" list(4191.470000 890.000000) nil)@@@list("iris_chen" "2017/08/22 17:13:08" nil "P16C000357-PC" "5n-armani13.a00")@@@list("anson_lee" "2017/08/24 14:21:35" nil "P172000029-PC" "5n-armani13.a00.0824") | list("[Spacing] VCC" "133.Shape to Thru Via" "5 MIL [DEFAULT]" "0 MIL" "5.00 MIL" "DRC ERROR CLASS/VCC" "[ThruVia] GND (VIA20D10A30) (4188.35 899.5)" "[Vcc Shape] +5VSB ((381.0 745.0) (7865.0 3971.0))" list(4198.340000 900.000000) nil)@@@list("iris_chen" "2017/08/22 17:17:49" nil "P16C000357-PC" "5n-armani13.a00")@@@list("anson_lee" "2017/08/24 14:22:20" nil "P172000029-PC" "5n-armani13.a00.0824") | list("[Spacing] VCC" "138.Shape to Thru Via" "5 MIL [DEFAULT]" "0 MIL" "5.00 MIL" "DRC ERROR CLASS/VCC" "[ThruVia] KB_LED_BL_DET (VIA20D10A30) (4513.0 1088.0)" "[Vcc Shape] +5VSB ((381.0 745.0) (7865.0 3971.0))" list(4519.000000 1080.000000) nil)@@@list("iris_chen" "2017/08/22 17:17:52" nil "P16C000357-PC" "5n-armani13.a00")@@@list("anson_lee" "2017/08/24 14:22:23" nil "P172000029-PC" "5n-armani13.a00.0824") | list("[Spacing] VCC" "117.Shape to Thru Via" "5 MIL [DEFAULT]" "0 MIL" "5.00 MIL" "DRC ERROR CLASS/VCC" "[ThruVia] KB_LED_BL_DET (VIA20D10A30) (4513.0 1088.0)" "[Vcc Shape] +3P3VSB ((926.0 394.17) (8430.0 4743.0))" list(4522.800000 1090.000000) nil)@@@list("iris_chen" "2017/08/22 17:18:11" nil "P16C000357-PC" "5n-armani13.a00")@@@list("anson_lee" "2017/08/24 14:22:12" nil "P172000029-PC" "5n-armani13.a00.0824") | list("[Spacing] VCC" "139.Shape to Thru Via" "5 MIL [DEFAULT]" "0 MIL" "5.00 MIL" "DRC ERROR CLASS/VCC" "[ThruVia] SYS_PWROK (VIA20D10A30) (4638.0 1089.0)" "[Vcc Shape] +5VSB ((381.0 745.0) (7865.0 3971.0))" list(4642.360000 1080.000000) nil)@@@list("iris_chen" "2017/08/22 17:17:52" nil "P16C000357-PC" "5n-armani13.a00")@@@list("anson_lee" "2017/08/24 14:22:24" nil "P172000029-PC" "5n-armani13.a00.0824") | list("[Spacing] VCC" "118.Shape to Thru Via" "5 MIL [DEFAULT]" "0 MIL" "5.00 MIL" "DRC ERROR CLASS/VCC" "[ThruVia] SYS_PWROK (VIA20D10A30) (4638.0 1089.0)" "[Vcc Shape] +3P3VSB ((926.0 394.17) (8430.0 4743.0))" list(4647.950000 1090.000000) nil)@@@list("iris_chen" "2017/08/22 17:18:12" nil "P16C000357-PC" "5n-armani13.a00")@@@list("anson_lee" "2017/08/24 14:22:12" nil "P172000029-PC" "5n-armani13.a00.0824") | list("[Spacing] VCC" "106.Shape to Thru Via" "5 MIL [DEFAULT]" "0 MIL" "5.00 MIL" "DRC ERROR CLASS/VCC" "[ThruVia] GND (VIA30D18A40) (4657.0 4666.0)" "[Vcc Shape] +AC_BAT_SYS ((4285.0 2738.0) (7985.0 4762.0))" list(4670.270000 4673.000000) nil)@@@list("iris_chen" "2017/08/22 17:18:00" nil "P16C000357-PC" "5n-armani13.a00")@@@nil | list("[Spacing] VCC" "4.Shape to Thru Via" "5 MIL [DEFAULT]" "0 MIL" "5.00 MIL" "DRC ERROR CLASS/VCC" "[ThruVia] GND (VIA30D18A40) (4657.0 4666.0)" "[Vcc Shape] +AC_BAT_SYS ((4285.0 2797.0) (7871.0 4762.0))" list(4670.270000 4673.000000) nil)@@@list("iris_chen" "2017/08/24 17:06:49" nil "P16C000357-PC" "5n-armani13.a00")@@@list("anson_lee" "2017/08/24 14:21:56" nil "P172000029-PC" "5n-armani13.a00.0824") | list("[Spacing] VCC" "130.Shape to Thru Via" "5 MIL [DEFAULT]" "0 MIL" "5.00 MIL" "DRC ERROR CLASS/VCC" "[ThruVia] GND (VIA30D18A40) (4657.0 4666.0)" "[Vcc Shape] +3P3VSB ((926.0 394.17) (8430.0 4743.0))" list(4671.700000 4663.000000) nil)@@@list("iris_chen" "2017/08/22 17:18:19" nil "P16C000357-PC" "5n-armani13.a00")@@@list("anson_lee" "2017/08/24 14:22:19" nil "P172000029-PC" "5n-armani13.a00.0824") | list("[Spacing] VCC" "107.Shape to Thru Via" "5 MIL [DEFAULT]" "0 MIL" "5.00 MIL" "DRC ERROR CLASS/VCC" "[ThruVia] GND (VIA30D18A40) (4696.0 4666.0)" "[Vcc Shape] +AC_BAT_SYS ((4285.0 2738.0) (7985.0 4762.0))" list(4709.270000 4673.000000) nil)@@@list("iris_chen" "2017/08/22 17:18:01" nil "P16C000357-PC" "5n-armani13.a00")@@@nil | list("[Spacing] VCC" "5.Shape to Thru Via" "5 MIL [DEFAULT]" "0 MIL" "5.00 MIL" "DRC ERROR CLASS/VCC" "[ThruVia] GND (VIA30D18A40) (4696.0 4666.0)" "[Vcc Shape] +AC_BAT_SYS ((4285.0 2797.0) (7871.0 4762.0))" list(4709.270000 4673.000000) nil)@@@list("iris_chen" "2017/08/24 17:06:50" nil "P16C000357-PC" "5n-armani13.a00")@@@list("anson_lee" "2017/08/24 14:21:57" nil "P172000029-PC" "5n-armani13.a00.0824") | list("[Spacing] VCC" "131.Shape to Thru Via" "5 MIL [DEFAULT]" "0 MIL" "5.00 MIL" "DRC ERROR CLASS/VCC" "[ThruVia] GND (VIA30D18A40) (4696.0 4666.0)" "[Vcc Shape] +3P3VSB ((926.0 394.17) (8430.0 4743.0))" list(4710.700000 4663.000000) nil)@@@list("iris_chen" "2017/08/22 17:18:20" nil "P16C000357-PC" "5n-armani13.a00")@@@list("anson_lee" "2017/08/24 14:22:19" nil "P172000029-PC" "5n-armani13.a00.0824") | list("[Spacing] VCC" "140.Shape to Thru Via" "5 MIL [DEFAULT]" "0 MIL" "5.00 MIL" "DRC ERROR CLASS/VCC" "[ThruVia] HDD_EN_PCH (VIA20D10A30) (4729.0 1089.0)" "[Vcc Shape] +5VSB ((381.0 745.0) (7865.0 3971.0))" list(4733.360000 1080.000000) nil)@@@list("iris_chen" "2017/08/22 17:17:53" nil "P16C000357-PC" "5n-armani13.a00")@@@list("anson_lee" "2017/08/24 14:22:24" nil "P172000029-PC" "5n-armani13.a00.0824") | list("[Spacing] VCC" "119.Shape to Thru Via" "5 MIL [DEFAULT]" "0 MIL" "5.00 MIL" "DRC ERROR CLASS/VCC" "[ThruVia] HDD_EN_PCH (VIA20D10A30) (4729.0 1089.0)" "[Vcc Shape] +3P3VSB ((926.0 394.17) (8430.0 4743.0))" list(4738.950000 1090.000000) nil)@@@list("iris_chen" "2017/08/22 17:18:12" nil "P16C000357-PC" "5n-armani13.a00")@@@list("anson_lee" "2017/08/24 14:22:13" nil "P172000029-PC" "5n-armani13.a00.0824") | list("[Spacing] VCC" "83.Shape to Thru Via" "5 MIL [(16|20|20|20)]" "0 MIL" "5.00 MIL" "DRC ERROR CLASS/VCC" "[ThruVia] PCIE3_GPU_TXN (VIA18D10A28) (4851.06 1953.0)" "[Vcc Shape] VCCPRIM ((4355.0 1425.0) (5177.0 1960.0))" list(4852.770000 1944.160000) nil)@@@list("iris_chen" "2017/08/22 17:18:07" nil "P16C000357-PC" "5n-armani13.a00")@@@list("anson_lee" "2017/08/24 14:21:45" nil "P172000029-PC" "5n-armani13.a00.0824") | list("[Spacing] VCC" "70.Shape to Thru Via" "5 MIL [(16|20|20|20)]" "0 MIL" "5.00 MIL" "DRC ERROR CLASS/VCC" "[ThruVia] PCIE3_GPU_TXN (VIA18D10A28) (4851.06 1953.0)" "[Vcc Shape] +VCCSA ((4227.0 1655.0) (5370.0 2182.0))" list(4859.880000 1951.200000) nil)@@@list("iris_chen" "2017/08/22 17:17:58" nil "P16C000357-PC" "5n-armani13.a00")@@@list("anson_lee" "2017/08/24 14:21:38" nil "P172000029-PC" "5n-armani13.a00.0824") | list("[Spacing] VCC" "81.Shape to Thru Via" "5 MIL [DEFAULT]" "0 MIL" "5.00 MIL" "DRC ERROR CLASS/VCC" "[ThruVia] VCCAMPHYPLL_1P0 (VIA18D10A28) (4857.0 1485.0)" "[Vcc Shape] VCCPRIM ((4355.0 1425.0) (5177.0 1960.0))" list(4864.480000 1490.000000) nil)@@@list("iris_chen" "2017/08/22 17:18:06" nil "P16C000357-PC" "5n-armani13.a00")@@@list("anson_lee" "2017/08/24 14:21:44" nil "P172000029-PC" "5n-armani13.a00.0824") | list("[Spacing] VCC" "86.Shape to Thru Via" "5 MIL [DEFAULT]" "0 MIL" "5.00 MIL" "DRC ERROR CLASS/VCC" "[ThruVia] VCCAMPHYPLL_1P0 (VIA18D10A28) (4857.0 1485.0)" "[Vcc Shape] +VCCIO ((3836.0 1141.93) (5170.0 2510.0))" list(4864.480000 1480.000000) nil)@@@list("iris_chen" "2017/08/22 17:18:03" nil "P16C000357-PC" "5n-armani13.a00")@@@list("anson_lee" "2017/08/24 14:21:47" nil "P172000029-PC" "5n-armani13.a00.0824") | list("[Spacing] VCC" "80.Shape to Thru Via" "5 MIL [DEFAULT]" "0 MIL" "5.00 MIL" "DRC ERROR CLASS/VCC" "[ThruVia] GND (VIA20D10A30) (5086.0 1419.0)" "[Vcc Shape] VCCPRIM ((4355.0 1425.0) (5177.0 1960.0))" list(5094.000000 1425.000000) nil)@@@list("iris_chen" "2017/08/22 17:18:05" nil "P16C000357-PC" "5n-armani13.a00")@@@list("anson_lee" "2017/08/24 14:21:44" nil "P172000029-PC" "5n-armani13.a00.0824") | list("[Spacing] VCC" "85.Shape to Thru Via" "5 MIL [DEFAULT]" "0 MIL" "5.00 MIL" "DRC ERROR CLASS/VCC" "[ThruVia] GND (VIA20D10A30) (5086.0 1419.0)" "[Vcc Shape] +VCCIO ((3836.0 1141.93) (5170.0 2510.0))" list(5095.170000 1415.000000) nil)@@@list("iris_chen" "2017/08/22 17:18:03" nil "P16C000357-PC" "5n-armani13.a00")@@@list("anson_lee" "2017/08/24 14:21:46" nil "P172000029-PC" "5n-armani13.a00.0824") | list("[Spacing] VCC" "82.Shape to Thru Via" "5 MIL [DEFAULT]" "0 MIL" "5.00 MIL" "DRC ERROR CLASS/VCC" "[ThruVia] +3VSUS_ORG (VIA20D10A30) (5160.0 1564.0)" "[Vcc Shape] VCCPRIM ((4355.0 1425.0) (5177.0 1960.0))" list(5157.640000 1573.720000) nil)@@@list("iris_chen" "2017/08/22 17:18:06" nil "P16C000357-PC" "5n-armani13.a00")@@@list("anson_lee" "2017/08/24 14:21:45" nil "P172000029-PC" "5n-armani13.a00.0824") | list("[Spacing] VCC" "91.Shape to Thru Via" "5 MIL [DEFAULT]" "0 MIL" "5.00 MIL" "DRC ERROR CLASS/VCC" "[ThruVia] +3VSUS_ORG (VIA20D10A30) (5160.0 1564.0)" "[Vcc Shape] +1VSB ((5160.0 1362.0) (6405.0 2495.0))" list(5160.000000 1554.000000) nil)@@@list("iris_chen" "2017/08/22 17:18:20" nil "P16C000357-PC" "5n-armani13.a00")@@@list("anson_lee" "2017/08/24 14:21:51" nil "P172000029-PC" "5n-armani13.a00.0824") | list("[Spacing] VCC" "97.Shape to Thru Via" "5 MIL [(20)]" "0 MIL" "5.00 MIL" "DRC ERROR CLASS/VCC" "[ThruVia] +VCORE2_R_LG_D (VIA30D18A40) (5596.0 2811.0)" "[Vcc Shape] +VCORE ((4180.0 1944.9) (5622.0 3243.99))" list(5592.700000 2825.630000) nil)@@@list("iris_chen" "2017/08/22 17:17:49" nil "P16C000357-PC" "5n-armani13.a00")@@@list("anson_lee" "2017/08/24 14:21:55" nil "P172000029-PC" "5n-armani13.a00.0824") | list("[Spacing] VCC" "123.Shape to Thru Via" "5 MIL [(20)]" "0 MIL" "5.00 MIL" "DRC ERROR CLASS/VCC" "[ThruVia] +VCORE2_R_LG_D (VIA30D18A40) (5596.0 2811.0)" "[Vcc Shape] +3P3VSB ((926.0 394.17) (8430.0 4743.0))" list(5602.700000 2824.420000) nil)@@@list("iris_chen" "2017/08/22 17:18:15" nil "P16C000357-PC" "5n-armani13.a00")@@@list("anson_lee" "2017/08/24 14:22:15" nil "P172000029-PC" "5n-armani13.a00.0824") | list("[Spacing] VCC" "66.Shape to Thru Via" "5 MIL [DEFAULT]" "0 MIL" "5.00 MIL" "DRC ERROR CLASS/VCC" "[ThruVia] +3P3VSB (VIA20D10A30) (5627.0 1083.0)" "[Vcc Shape] +5V ((625.0 525.0) (8000.0 2265.0))" list(5633.000000 1075.000000) nil)@@@list("iris_chen" "2017/08/22 17:13:08" nil "P16C000357-PC" "5n-armani13.a00")@@@list("anson_lee" "2017/08/24 14:21:36" nil "P172000029-PC" "5n-armani13.a00.0824") | list("[Spacing] VCC" "141.Shape to Thru Via" "5 MIL [DEFAULT]" "0 MIL" "5.00 MIL" "DRC ERROR CLASS/VCC" "[ThruVia] +3P3VSB (VIA20D10A30) (5627.0 1083.0)" "[Vcc Shape] +5VSB ((381.0 745.0) (7865.0 3971.0))" list(5636.800000 1085.000000) nil)@@@list("iris_chen" "2017/08/22 17:17:53" nil "P16C000357-PC" "5n-armani13.a00")@@@list("anson_lee" "2017/08/24 14:22:25" nil "P172000029-PC" "5n-armani13.a00.0824") | list("[Spacing] VCC" "104.Shape to Thru Via" "5 MIL [DEFAULT]" "0 MIL" "5.00 MIL" "DRC ERROR CLASS/VCC" "[ThruVia] GND (VIA20D10A30) (5978.0 3436.0)" "[Vcc Shape] +VDDC_VGA ((5030.0 3445.0) (6395.0 4663.0))" list(5982.360000 3445.000000) nil)@@@list("iris_chen" "2017/08/22 17:18:22" nil "P16C000357-PC" "5n-armani13.a00")@@@list("anson_lee" "2017/08/24 14:22:00" nil "P172000029-PC" "5n-armani13.a00.0824") | list("[Spacing] VCC" "10.Shape to Thru Via" "5 MIL [DEFAULT]" "0 MIL" "5.00 MIL" "DRC ERROR CLASS/VCC" "[ThruVia] GND (VIA20D10A30) (5978.0 3436.0)" "[Vcc Shape] +FBVDDQ ((5939.97 3013.0) (7767.0 4661.0))" list(5987.950000 3435.000000) nil)@@@list("iris_chen" "2017/08/24 17:06:54" nil "P16C000357-PC" "5n-armani13.a00")@@@list("anson_lee" "2017/08/24 14:21:40" nil "P172000029-PC" "5n-armani13.a00.0824") | list("[Spacing] VCC" "56.Shape to Thru Via" "5 MIL [DEFAULT]" "0 MIL" "5.00 MIL" "DRC ERROR CLASS/VCC" "[ThruVia] GND (VIA20D10A30) (5978.0 3436.0)" "[Vcc Shape] +FBVDDQ ((5939.97 3015.0) (7780.0 4661.0))" list(5987.950000 3435.000000) nil)@@@list("iris_chen" "2017/08/22 17:13:13" nil "P16C000357-PC" "5n-armani13.a00")@@@nil | list("[Spacing] VCC" "103.Shape to Thru Via" "5 MIL [DEFAULT]" "0 MIL" "5.00 MIL" "DRC ERROR CLASS/VCC" "[ThruVia] GND (VIA20D10A30) (6011.0 3436.0)" "[Vcc Shape] +VDDC_VGA ((5030.0 3445.0) (6395.0 4663.0))" list(6015.360000 3445.000000) nil)@@@list("iris_chen" "2017/08/22 17:18:21" nil "P16C000357-PC" "5n-armani13.a00")@@@list("anson_lee" "2017/08/24 14:21:59" nil "P172000029-PC" "5n-armani13.a00.0824") | list("[Spacing] VCC" "55.Shape to Thru Via" "5 MIL [DEFAULT]" "0 MIL" "5.00 MIL" "DRC ERROR CLASS/VCC" "[ThruVia] GND (VIA20D10A30) (6011.0 3436.0)" "[Vcc Shape] +FBVDDQ ((5939.97 3015.0) (7780.0 4661.0))" list(6020.950000 3435.000000) nil)@@@list("iris_chen" "2017/08/22 17:13:13" nil "P16C000357-PC" "5n-armani13.a00")@@@nil | list("[Spacing] VCC" "9.Shape to Thru Via" "5 MIL [DEFAULT]" "0 MIL" "5.00 MIL" "DRC ERROR CLASS/VCC" "[ThruVia] GND (VIA20D10A30) (6011.0 3436.0)" "[Vcc Shape] +FBVDDQ ((5939.97 3013.0) (7767.0 4661.0))" list(6020.950000 3435.000000) nil)@@@list("iris_chen" "2017/08/24 17:06:54" nil "P16C000357-PC" "5n-armani13.a00")@@@list("anson_lee" "2017/08/24 14:21:39" nil "P172000029-PC" "5n-armani13.a00.0824") | list("[Spacing] VCC" "11.Shape to Thru Via" "5 MIL [DEFAULT]" "0 MIL" "5.00 MIL" "DRC ERROR CLASS/VCC" "[ThruVia] GPU_DBG_DATA0 (VIA20D10A30) (6060.0 3443.0)" "[Vcc Shape] +FBVDDQ ((5939.97 3013.0) (7767.0 4661.0))" list(6066.000000 3435.000000) nil)@@@list("iris_chen" "2017/08/24 17:06:55" nil "P16C000357-PC" "5n-armani13.a00")@@@list("anson_lee" "2017/08/24 14:21:40" nil "P172000029-PC" "5n-armani13.a00.0824") | list("[Spacing] VCC" "57.Shape to Thru Via" "5 MIL [DEFAULT]" "0 MIL" "5.00 MIL" "DRC ERROR CLASS/VCC" "[ThruVia] GPU_DBG_DATA0 (VIA20D10A30) (6060.0 3443.0)" "[Vcc Shape] +FBVDDQ ((5939.97 3015.0) (7780.0 4661.0))" list(6066.000000 3435.000000) nil)@@@list("iris_chen" "2017/08/22 17:13:14" nil "P16C000357-PC" "5n-armani13.a00")@@@nil | list("[Spacing] VCC" "105.Shape to Thru Via" "5 MIL [DEFAULT]" "0 MIL" "5.00 MIL" "DRC ERROR CLASS/VCC" "[ThruVia] GPU_DBG_DATA0 (VIA20D10A30) (6060.0 3443.0)" "[Vcc Shape] +VDDC_VGA ((5030.0 3445.0) (6395.0 4663.0))" list(6069.800000 3445.000000) nil)@@@list("iris_chen" "2017/08/22 17:18:22" nil "P16C000357-PC" "5n-armani13.a00")@@@list("anson_lee" "2017/08/24 14:22:00" nil "P172000029-PC" "5n-armani13.a00.0824") | list("[Spacing] VCC" "126.Shape to Thru Via" "5 MIL [DEFAULT]" "0 MIL" "5.00 MIL" "DRC ERROR CLASS/VCC" "[ThruVia] +3VS_VGA (VIA20D10A30) (6120.99 3215.01)" "[Vcc Shape] +3P3VSB ((926.0 394.17) (8430.0 4743.0))" list(6117.140000 3205.780000) nil)@@@list("iris_chen" "2017/08/22 17:18:17" nil "P16C000357-PC" "5n-armani13.a00")@@@list("anson_lee" "2017/08/24 14:22:17" nil "P172000029-PC" "5n-armani13.a00.0824") | list("[Spacing] VCC" "54.Shape to Thru Via" "5 MIL [DEFAULT]" "0 MIL" "5.00 MIL" "DRC ERROR CLASS/VCC" "[ThruVia] +3VS_VGA (VIA20D10A30) (6120.99 3215.01)" "[Vcc Shape] +FBVDDQ ((5939.97 3015.0) (7780.0 4661.0))" list(6128.580000 3208.490000) nil)@@@list("iris_chen" "2017/08/22 17:13:12" nil "P16C000357-PC" "5n-armani13.a00")@@@nil | list("[Spacing] VCC" "8.Shape to Thru Via" "5 MIL [DEFAULT]" "0 MIL" "5.00 MIL" "DRC ERROR CLASS/VCC" "[ThruVia] +3VS_VGA (VIA20D10A30) (6120.99 3215.01)" "[Vcc Shape] +FBVDDQ ((5939.97 3013.0) (7767.0 4661.0))" list(6128.580000 3208.490000) nil)@@@list("iris_chen" "2017/08/24 17:06:53" nil "P16C000357-PC" "5n-armani13.a00")@@@list("anson_lee" "2017/08/24 14:21:39" nil "P172000029-PC" "5n-armani13.a00.0824") | list("[Spacing] VCC" "156.Shape to Shape" "20 MIL [M_19V_20]" "10 MIL" "10.00 MIL" "DRC ERROR CLASS/VCC" "[Vcc Shape] +AC_BAT_SYS ((4285.0 2738.0) (7985.0 4762.0))" "[Vcc Shape] +VDDC_VGA ((5030.0 3445.0) (6395.0 4663.0))" list(6266.040000 4420.000000) nil)@@@list("iris_chen" "2017/08/22 17:18:23" nil "P16C000357-PC" "5n-armani13.a00")@@@nil | list("[Spacing] VCC" "2.Shape to Shape" "20 MIL [M_19V_20]" "10 MIL" "10.00 MIL" "DRC ERROR CLASS/VCC" "[Vcc Shape] +AC_BAT_SYS ((4285.0 2797.0) (7871.0 4762.0))" "[Vcc Shape] +VDDC_VGA ((5030.0 3445.0) (6395.0 4663.0))" list(6266.040000 4420.000000) nil)@@@list("iris_chen" "2017/08/24 17:06:47" nil "P16C000357-PC" "5n-armani13.a00")@@@list("anson_lee" "2017/08/24 14:22:01" nil "P172000029-PC" "5n-armani13.a00.0824") | list("[Spacing] VCC" "16.Shape to Shape" "20 MIL [M_19V_20]" "10 MIL" "10.00 MIL" "DRC ERROR CLASS/VCC" "[Vcc Shape] +AC_BAT_SYS ((4285.0 2797.0) (7871.0 4762.0))" "[Vcc Shape] +FBVDDQ ((5939.97 3013.0) (7767.0 4661.0))" list(6292.930000 4420.000000) nil)@@@list("iris_chen" "2017/08/24 17:06:59" nil "P16C000357-PC" "5n-armani13.a00")@@@list("anson_lee" "2017/08/24 14:21:43" nil "P172000029-PC" "5n-armani13.a00.0824") | list("[Spacing] VCC" "92.Shape to Thru Via" "5 MIL [DEFAULT]" "0 MIL" "5.00 MIL" "DRC ERROR CLASS/VCC" "[ThruVia] VCCSA_SENSE (VIA20D10A30) (6335.0 2119.0)" "[Vcc Shape] +1VSB ((5160.0 1362.0) (6405.0 2495.0))" list(6330.000000 2127.660000) nil)@@@list("iris_chen" "2017/08/22 17:18:21" nil "P16C000357-PC" "5n-armani13.a00")@@@list("anson_lee" "2017/08/24 14:21:51" nil "P172000029-PC" "5n-armani13.a00.0824") | list("[Spacing] VCC" "58.Shape to Thru Via" "5 MIL [DEFAULT]" "0 MIL" "5.00 MIL" "DRC ERROR CLASS/VCC" "[ThruVia] +0.95V_GPU (VIA20D10A30) (6341.0 3948.0)" "[Vcc Shape] +FBVDDQ ((5939.97 3015.0) (7780.0 4661.0))" list(6335.050000 3956.030000) nil)@@@list("iris_chen" "2017/08/22 17:13:14" nil "P16C000357-PC" "5n-armani13.a00")@@@nil | list("[Spacing] VCC" "106.Shape to Thru Via" "5 MIL [DEFAULT]" "0 MIL" "5.00 MIL" "DRC ERROR CLASS/VCC" "[ThruVia] +0.95V_GPU (VIA20D10A30) (6341.0 3948.0)" "[Vcc Shape] +VDDC_VGA ((5030.0 3445.0) (6395.0 4663.0))" list(6338.650000 3938.280000) nil)@@@list("iris_chen" "2017/08/22 17:18:23" nil "P16C000357-PC" "5n-armani13.a00")@@@list("anson_lee" "2017/08/24 14:22:01" nil "P172000029-PC" "5n-armani13.a00.0824") | list("[Spacing] VCC" "56.Shape to Thru Via" "5 MIL [DEFAULT]" "0 MIL" "5.00 MIL" "DRC ERROR CLASS/VCC" "[ThruVia] VCCSA_SENSE (VIA20D10A30) (6335.0 2119.0)" "[Vcc Shape] GND ((6340.0 1914.0) (7486.0 2495.0))" list(6340.000000 2127.660000) nil)@@@list("iris_chen" "2017/08/22 17:13:20" nil "P16C000357-PC" "5n-armani13.a00")@@@list("anson_lee" "2017/08/24 14:21:30" nil "P172000029-PC" "5n-armani13.a00.0824") | list("[Spacing] VCC" "12.Shape to Thru Via" "5 MIL [DEFAULT]" "0 MIL" "5.00 MIL" "DRC ERROR CLASS/VCC" "[ThruVia] +0.95V_GPU (VIA20D10A30) (6341.0 3948.0)" "[Vcc Shape] +FBVDDQ ((5939.97 3013.0) (7767.0 4661.0))" list(6348.720000 3941.650000) nil)@@@list("iris_chen" "2017/08/24 17:06:56" nil "P16C000357-PC" "5n-armani13.a00")@@@list("anson_lee" "2017/08/24 14:21:41" nil "P172000029-PC" "5n-armani13.a00.0824") | list("[Spacing] VCC" "55.Shape to Thru Via" "5 MIL [DEFAULT]" "0 MIL" "5.00 MIL" "DRC ERROR CLASS/VCC" "[ThruVia] +VCCSA (VIA20D10A30) (6521.0 1919.0)" "[Vcc Shape] GND ((6340.0 1914.0) (7486.0 2495.0))" list(6529.000000 1925.000000) nil)@@@list("iris_chen" "2017/08/22 17:13:20" nil "P16C000357-PC" "5n-armani13.a00")@@@list("anson_lee" "2017/08/24 14:21:29" nil "P172000029-PC" "5n-armani13.a00.0824") | list("[Spacing] VCC" "146.Shape to Thru Via" "5 MIL [DEFAULT]" "0 MIL" "5.00 MIL" "DRC ERROR CLASS/VCC" "[ThruVia] +VCCSA (VIA20D10A30) (6521.0 1919.0)" "[Vcc Shape] +5VSB ((381.0 745.0) (7865.0 3971.0))" list(6530.170000 1915.000000) nil)@@@list("iris_chen" "2017/08/22 17:17:56" nil "P16C000357-PC" "5n-armani13.a00")@@@list("anson_lee" "2017/08/24 14:22:37" nil "P172000029-PC" "5n-armani13.a00.0824") | list("[Spacing] VCC" "108.Shape to Thru Via" "5 MIL [DEFAULT]" "0 MIL" "5.00 MIL" "DRC ERROR CLASS/VCC" "[ThruVia] GND (VIA20D10A30) (6713.0 4603.0)" "[Vcc Shape] +AC_BAT_SYS ((4285.0 2738.0) (7985.0 4762.0))" list(6710.640000 4612.720000) nil)@@@list("iris_chen" "2017/08/22 17:18:01" nil "P16C000357-PC" "5n-armani13.a00")@@@nil | list("[Spacing] VCC" "6.Shape to Thru Via" "5 MIL [DEFAULT]" "0 MIL" "5.00 MIL" "DRC ERROR CLASS/VCC" "[ThruVia] GND (VIA20D10A30) (6713.0 4603.0)" "[Vcc Shape] +AC_BAT_SYS ((4285.0 2797.0) (7871.0 4762.0))" list(6710.640000 4612.720000) nil)@@@list("iris_chen" "2017/08/24 17:06:51" nil "P16C000357-PC" "5n-armani13.a00")@@@list("anson_lee" "2017/08/24 14:21:58" nil "P172000029-PC" "5n-armani13.a00.0824") | list("[Spacing] VCC" "14.Shape to Thru Via" "5 MIL [DEFAULT]" "0 MIL" "5.00 MIL" "DRC ERROR CLASS/VCC" "[ThruVia] GND (VIA20D10A30) (6713.0 4603.0)" "[Vcc Shape] +FBVDDQ ((5939.97 3013.0) (7767.0 4661.0))" list(6721.030000 4608.960000) nil)@@@list("iris_chen" "2017/08/24 17:06:57" nil "P16C000357-PC" "5n-armani13.a00")@@@list("anson_lee" "2017/08/24 14:21:42" nil "P172000029-PC" "5n-armani13.a00.0824") | list("[Spacing] VCC" "60.Shape to Thru Via" "5 MIL [DEFAULT]" "0 MIL" "5.00 MIL" "DRC ERROR CLASS/VCC" "[ThruVia] GND (VIA20D10A30) (6713.0 4603.0)" "[Vcc Shape] +FBVDDQ ((5939.97 3015.0) (7780.0 4661.0))" list(6721.030000 4608.960000) nil)@@@list("iris_chen" "2017/08/22 17:13:16" nil "P16C000357-PC" "5n-armani13.a00")@@@nil | list("[Spacing] VCC" "15.Shape to Thru Via" "5 MIL [DEFAULT]" "0 MIL" "5.00 MIL" "DRC ERROR CLASS/VCC" "[ThruVia] +3P3VSB (VIA20D10A30) (7008.0 4616.0)" "[Vcc Shape] +FBVDDQ ((5939.97 3013.0) (7767.0 4661.0))" list(7007.920000 4606.000000) nil)@@@list("iris_chen" "2017/08/24 17:06:58" nil "P16C000357-PC" "5n-armani13.a00")@@@list("anson_lee" "2017/08/24 14:21:42" nil "P172000029-PC" "5n-armani13.a00.0824") | list("[Spacing] VCC" "61.Shape to Thru Via" "5 MIL [DEFAULT]" "0 MIL" "5.00 MIL" "DRC ERROR CLASS/VCC" "[ThruVia] +3P3VSB (VIA20D10A30) (7008.0 4616.0)" "[Vcc Shape] +FBVDDQ ((5939.97 3015.0) (7780.0 4661.0))" list(7007.920000 4606.000000) nil)@@@list("iris_chen" "2017/08/22 17:13:16" nil "P16C000357-PC" "5n-armani13.a00")@@@nil | list("[Spacing] VCC" "109.Shape to Thru Via" "20 MIL [M_19V_20]" "0 MIL" "20.00 MIL" "DRC ERROR CLASS/VCC" "[ThruVia] +3P3VSB (VIA20D10A30) (7008.0 4616.0)" "[Vcc Shape] +AC_BAT_SYS ((4285.0 2738.0) (7985.0 4762.0))" list(7016.810000 4611.270000) nil)@@@list("iris_chen" "2017/08/22 17:18:02" nil "P16C000357-PC" "5n-armani13.a00")@@@nil | list("[Spacing] VCC" "7.Shape to Thru Via" "20 MIL [M_19V_20]" "0 MIL" "20.00 MIL" "DRC ERROR CLASS/VCC" "[ThruVia] +3P3VSB (VIA20D10A30) (7008.0 4616.0)" "[Vcc Shape] +AC_BAT_SYS ((4285.0 2797.0) (7871.0 4762.0))" list(7016.810000 4611.270000) nil)@@@list("iris_chen" "2017/08/24 17:06:52" nil "P16C000357-PC" "5n-armani13.a00")@@@list("anson_lee" "2017/08/24 14:21:58" nil "P172000029-PC" "5n-armani13.a00.0824") | list("[Spacing] VCC" "13.Shape to Thru Via" "5 MIL [DEFAULT]" "0 MIL" "5.00 MIL" "DRC ERROR CLASS/VCC" "[ThruVia] GND (VIA20D10A30) (7033.0 4588.0)" "[Vcc Shape] +FBVDDQ ((5939.97 3013.0) (7767.0 4661.0))" list(7035.580000 4578.340000) nil)@@@list("iris_chen" "2017/08/24 17:06:57" nil "P16C000357-PC" "5n-armani13.a00")@@@list("anson_lee" "2017/08/24 14:21:41" nil "P172000029-PC" "5n-armani13.a00.0824") | list("[Spacing] VCC" "59.Shape to Thru Via" "5 MIL [DEFAULT]" "0 MIL" "5.00 MIL" "DRC ERROR CLASS/VCC" "[ThruVia] GND (VIA20D10A30) (7033.0 4588.0)" "[Vcc Shape] +FBVDDQ ((5939.97 3015.0) (7780.0 4661.0))" list(7035.580000 4578.340000) nil)@@@list("iris_chen" "2017/08/22 17:13:15" nil "P16C000357-PC" "5n-armani13.a00")@@@nil | list("[Spacing] VCC" "105.Shape to Thru Via" "5 MIL [DEFAULT]" "0 MIL" "5.00 MIL" "DRC ERROR CLASS/VCC" "[ThruVia] GND (VIA20D10A30) (7033.0 4588.0)" "[Vcc Shape] +AC_BAT_SYS ((4285.0 2738.0) (7985.0 4762.0))" list(7042.660000 4585.410000) nil)@@@list("iris_chen" "2017/08/22 17:18:00" nil "P16C000357-PC" "5n-armani13.a00")@@@nil | list("[Spacing] VCC" "3.Shape to Thru Via" "5 MIL [DEFAULT]" "0 MIL" "5.00 MIL" "DRC ERROR CLASS/VCC" "[ThruVia] GND (VIA20D10A30) (7033.0 4588.0)" "[Vcc Shape] +AC_BAT_SYS ((4285.0 2797.0) (7871.0 4762.0))" list(7042.660000 4585.410000) nil)@@@list("iris_chen" "2017/08/24 17:06:49" nil "P16C000357-PC" "5n-armani13.a00")@@@list("anson_lee" "2017/08/24 14:21:56" nil "P172000029-PC" "5n-armani13.a00.0824") | list("[Spacing] VCC" "67.Shape to Thru Via" "5 MIL [DEFAULT]" "0 MIL" "5.00 MIL" "DRC ERROR CLASS/VCC" "[ThruVia] GND (VIA20D10A30) (7338.0 1070.15)" "[Vcc Shape] +5V ((625.0 525.0) (8000.0 2265.0))" list(7339.730000 1080.000000) nil)@@@list("iris_chen" "2017/08/22 17:13:09" nil "P16C000357-PC" "5n-armani13.a00")@@@list("anson_lee" "2017/08/24 14:21:36" nil "P172000029-PC" "5n-armani13.a00.0824") | list("[Spacing] VCC" "93.Shape to Thru Via" "5 MIL [DEFAULT]" "0 MIL" "5.00 MIL" "DRC ERROR CLASS/VCC" "[ThruVia] GND (VIA20D10A30) (7338.0 1070.15)" "[Vcc Shape] +3P3V ((6950.0 850.0) (8205.0 1355.0))" list(7348.000000 1070.000000) nil)@@@list("iris_chen" "2017/08/22 17:13:11" nil "P16C000357-PC" "5n-armani13.a00")@@@list("anson_lee" "2017/08/24 14:21:52" nil "P172000029-PC" "5n-armani13.a00.0824") | list("[Spacing] VCC" "94.Shape to Thru Via" "5 MIL [(15)]" "0 MIL" "5.00 MIL" "DRC ERROR CLASS/VCC" "[ThruVia] CLKPCIE_LAN_N3 (NBT26B20D10A30_68) (7450.0 1075.07)" "[Vcc Shape] +3P3V ((6950.0 850.0) (8205.0 1355.0))" list(7458.620000 1070.000000) nil)@@@list("iris_chen" "2017/08/22 17:13:11" nil "P16C000357-PC" "5n-armani13.a00")@@@list("anson_lee" "2017/08/24 14:21:53" nil "P172000029-PC" "5n-armani13.a00.0824") | list("[Spacing] VCC" "68.Shape to Thru Via" "5 MIL [(15)]" "0 MIL" "5.00 MIL" "DRC ERROR CLASS/VCC" "[ThruVia] CLKPCIE_LAN_N3 (NBT26B20D10A30_68) (7450.0 1075.07)" "[Vcc Shape] +5V ((625.0 525.0) (8000.0 2265.0))" list(7458.700000 1080.000000) nil)@@@list("iris_chen" "2017/08/22 17:13:09" nil "P16C000357-PC" "5n-armani13.a00")@@@list("anson_lee" "2017/08/24 14:21:37" nil "P172000029-PC" "5n-armani13.a00.0824") | list("[Spacing] VCC" "95.Shape to Thru Via" "5 MIL [(15)]" "0 MIL" "5.00 MIL" "DRC ERROR CLASS/VCC" "[ThruVia] CLKPCIE_LAN_P3 (NBT20B26D10A30_68) (7479.0 1078.0)" "[Vcc Shape] +3P3V ((6950.0 850.0) (8205.0 1355.0))" list(7485.000000 1070.000000) nil)@@@list("iris_chen" "2017/08/22 17:13:12" nil "P16C000357-PC" "5n-armani13.a00")@@@list("anson_lee" "2017/08/24 14:21:54" nil "P172000029-PC" "5n-armani13.a00.0824") | list("[Spacing-SameNet] VCC" "193.Shape to Thru Via Same Net" "5 MIL [DEFAULT]" "0 MIL" "5.00 MIL" "DRC ERROR CLASS/VCC" "[ThruVia] GND (VIA20D10A30) (7488.0 2356.0)" "[Vcc Shape] GND ((6340.0 1914.0) (7486.0 2495.0))" list(7486.000000 2365.800000) nil)@@@list("iris_chen" "2017/08/22 17:18:43" nil "P16C000357-PC" "5n-armani13.a00")@@@list("anson_lee" "2017/08/24 14:24:01" nil "P172000029-PC" "5n-armani13.a00.0824") | list("[Spacing] VCC" "69.Shape to Thru Via" "5 MIL [(15)]" "0 MIL" "5.00 MIL" "DRC ERROR CLASS/VCC" "[ThruVia] CLKPCIE_LAN_P3 (NBT20B26D10A30_68) (7479.0 1078.0)" "[Vcc Shape] +5V ((625.0 525.0) (8000.0 2265.0))" list(7488.800000 1080.000000) nil)@@@list("iris_chen" "2017/08/22 17:13:10" nil "P16C000357-PC" "5n-armani13.a00")@@@list("anson_lee" "2017/08/24 14:21:38" nil "P172000029-PC" "5n-armani13.a00.0824") | list("[Spacing] VCC" "122.Shape to Thru Via" "5 MIL [DEFAULT]" "0 MIL" "5.00 MIL" "DRC ERROR CLASS/VCC" "[ThruVia] GND (VIA20D10A30) (7488.0 2356.0)" "[Vcc Shape] +3P3VSB ((926.0 394.17) (8430.0 4743.0))" list(7496.000000 2362.000000) nil)@@@list("iris_chen" "2017/08/22 17:18:14" nil "P16C000357-PC" "5n-armani13.a00")@@@list("anson_lee" "2017/08/24 14:22:15" nil "P172000029-PC" "5n-armani13.a00.0824") | list("[Spacing] VCC" "103.Shape to Thru Via" "5 MIL [DEFAULT]" "0 MIL" "5.00 MIL" "DRC ERROR CLASS/VCC" "[ThruVia] GND (VIA20D10A30) (7600.0 2737.0)" "[Vcc Shape] +AC_BAT_SYS ((4285.0 2738.0) (7985.0 4762.0))" list(7597.410000 2746.660000) nil)@@@list("iris_chen" "2017/08/22 17:17:59" nil "P16C000357-PC" "5n-armani13.a00")@@@nil | list("[Spacing] VCC" "136.Shape to Thru Via" "5 MIL [DEFAULT]" "0 MIL" "5.00 MIL" "DRC ERROR CLASS/VCC" "[ThruVia] GND (VIA20D10A30) (7600.0 2737.0)" "[Vcc Shape] +3P3VSB ((926.0 394.17) (8430.0 4743.0))" list(7604.360000 2728.000000) nil)@@@list("iris_chen" "2017/08/22 17:18:14" nil "P16C000357-PC" "5n-armani13.a00")@@@nil | list("[Spacing] VCC" "137.Shape to Thru Via" "5 MIL [DEFAULT]" "0 MIL" "5.00 MIL" "DRC ERROR CLASS/VCC" "[ThruVia] GND (VIA20D10A30) (7655.0 2737.0)" "[Vcc Shape] +3P3VSB ((926.0 394.17) (8430.0 4743.0))" list(7659.360000 2728.000000) nil)@@@list("iris_chen" "2017/08/22 17:18:15" nil "P16C000357-PC" "5n-armani13.a00")@@@nil | list("[Spacing] VCC" "104.Shape to Thru Via" "5 MIL [DEFAULT]" "0 MIL" "5.00 MIL" "DRC ERROR CLASS/VCC" "[ThruVia] GND (VIA20D10A30) (7655.0 2737.0)" "[Vcc Shape] +AC_BAT_SYS ((4285.0 2738.0) (7985.0 4762.0))" list(7664.950000 2738.000000) nil)@@@list("iris_chen" "2017/08/22 17:17:59" nil "P16C000357-PC" "5n-armani13.a00")@@@nil | list("[Spacing] VCC" "62.Shape to Shape" "20 MIL [M_19V_20]" "10 MIL" "10.00 MIL" "DRC ERROR CLASS/VCC" "[Vcc Shape] +AC_BAT_SYS ((4285.0 2738.0) (7985.0 4762.0))" "[Vcc Shape] +FBVDDQ ((5939.97 3015.0) (7780.0 4661.0))" list(7790.000000 3027.090000) nil)@@@list("iris_chen" "2017/08/22 17:13:17" nil "P16C000357-PC" "5n-armani13.a00")@@@nil | list("[Spacing] VCC" "1.Shape to Shape" "20 MIL [M_19V_20]" "10 MIL" "10.00 MIL" "DRC ERROR CLASS/VCC" "[Vcc Shape] +AC_BAT_SYS ((4285.0 2797.0) (7871.0 4762.0))" "[Vcc Shape] +3P3VSB ((926.0 394.17) (8430.0 4743.0))" list(7871.000000 3000.000000) nil)@@@list("iris_chen" "2017/08/24 17:06:46" nil "P16C000357-PC" "5n-armani13.a00")@@@list("anson_lee" "2017/08/24 14:22:20" nil "P172000029-PC" "5n-armani13.a00.0824") | list("[Spacing] VCC" "149.Shape to Shape" "20 MIL [M_19V_20]" "10 MIL" "10.00 MIL" "DRC ERROR CLASS/VCC" "[Vcc Shape] +AC_BAT_SYS ((4285.0 2738.0) (7985.0 4762.0))" "[Vcc Shape] +3P3VSB ((926.0 394.17) (8430.0 4743.0))" list(7967.930000 2945.000000) nil)@@@list("iris_chen" "2017/08/22 17:18:20" nil "P16C000357-PC" "5n-armani13.a00")@@@nil | list("[Spacing] VCC" "139.Shape to Thru Via" "5 MIL [(15)]" "0 MIL" "5.00 MIL" "DRC ERROR CLASS/VCC" "[ThruVia] CLK_PCIE_PEG_REQ# (VIA20D10A30) (8067.25 2847.0)" "[Vcc Shape] +3P3VSB ((926.0 394.17) (8430.0 4743.0))" list(8057.350000 2845.580000) nil)@@@list("iris_chen" "2017/08/22 17:18:15" nil "P16C000357-PC" "5n-armani13.a00")@@@nil | list("[Spacing] VCC" "71.Shape to Thru Via" "5 MIL [DEFAULT]" "0 MIL" "5.00 MIL" "DRC ERROR CLASS/VCC" "[ThruVia] CLK_PCIE_PEG_REQ# (VIA20D10A30) (8067.25 2847.0)" "[Vcc Shape] GND ((-191.01 273.9) (8699.38 4792.96))" list(8074.960000 2840.630000) nil)@@@list("iris_chen" "2017/08/22 17:13:24" nil "P16C000357-PC" "5n-armani13.a00")@@@nil | list("[Spacing] VCC" "113.Shape to Thru Via" "5 MIL [(12)]" "0 MIL" "5.00 MIL" "DRC ERROR CLASS/VCC" "[ThruVia] PCIE11_SSD1_TXP (VIA20D10A30) (8191.0 764.0)" "[Vcc Shape] +3P3VSB ((926.0 394.17) (8430.0 4743.0))" list(8184.680000 771.750000) nil)@@@list("iris_chen" "2017/08/22 17:18:09" nil "P16C000357-PC" "5n-armani13.a00")@@@list("anson_lee" "2017/08/24 14:22:09" nil "P172000029-PC" "5n-armani13.a00.0824") | list("[Spacing] VCC" "42.Shape to Thru Via" "5 MIL [DEFAULT]" "0 MIL" "5.00 MIL" "DRC ERROR CLASS/VCC" "[ThruVia] PCIE11_SSD1_TXP (VIA20D10A30) (8191.0 764.0)" "[Vcc Shape] GND ((-191.01 273.9) (8699.38 4792.96))" list(8198.110000 771.030000) nil)@@@list("iris_chen" "2017/08/22 17:13:23" nil "P16C000357-PC" "5n-armani13.a00")@@@list("anson_lee" "2017/08/24 14:21:21" nil "P172000029-PC" "5n-armani13.a00.0824")
